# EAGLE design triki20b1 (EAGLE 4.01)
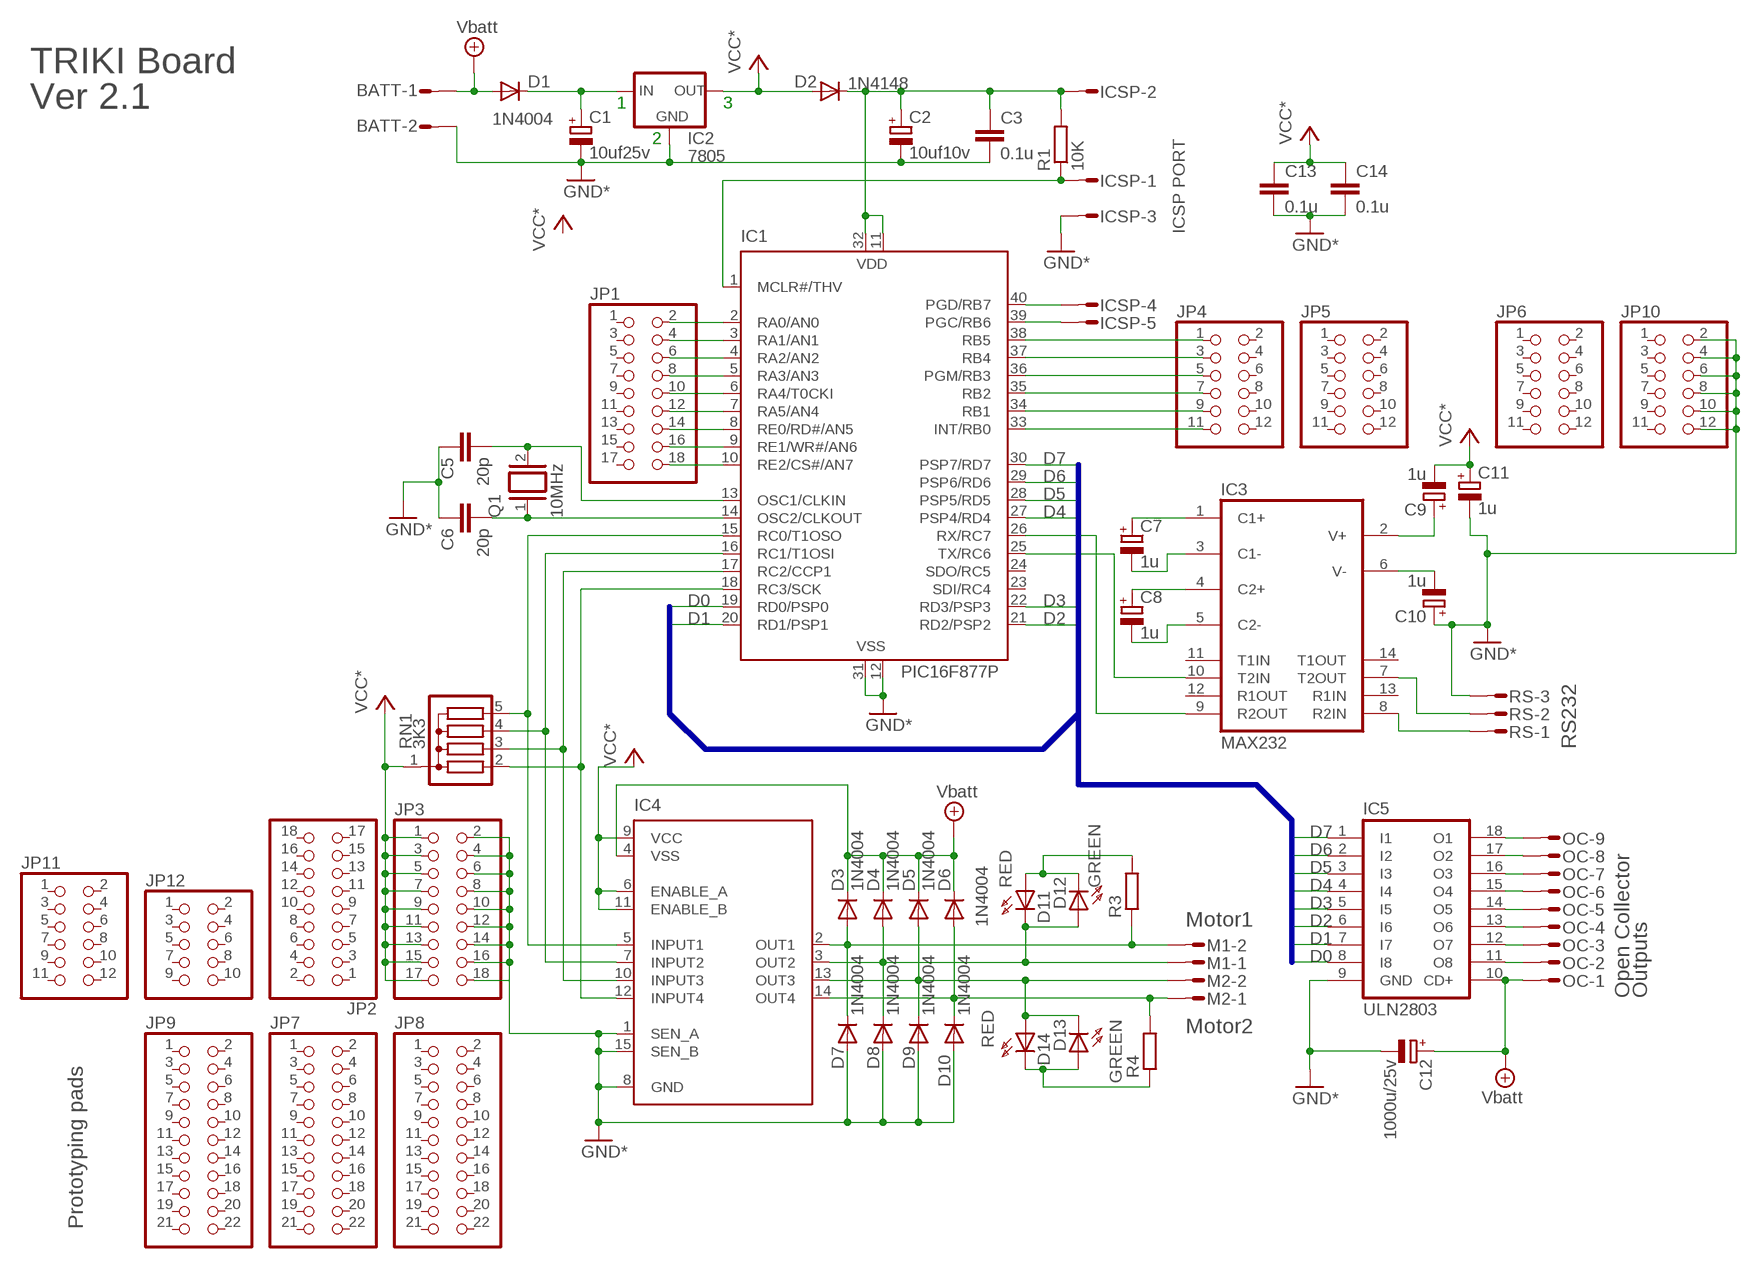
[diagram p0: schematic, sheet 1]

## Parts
BATT  S02P  [S02P]
C1  10uf25v  CPOL-EUE2-4  [E2-4]
C2  10uf10v  CPOL-EUE2-4  [E2-4]
C3  0.1u  C-EU025-025X050  [C025-025X050]
C5  20p  C-EU025-024X044  [C025-024X044]
C6  20p  C-EU025-024X044  [C025-024X044]
C7  1u  CPOL-EUE2-4  [E2-4]
C8  1u  CPOL-EUE2-4  [E2-4]
C9  1u  CPOL-EUE2-4  [E2-4]
C10  1u  CPOL-EUE2-4  [E2-4]
C11  1u  CPOL-EUE2-4  [E2-4]
C12  1000u/25v  CPOL-EUE3.5-10  [E3,5-10]
C13  0.1u  C-EU025-025X050  [C025-025X050]
C14  0.1u  C-EU025-025X050  [C025-025X050]
D1  1N4004  [DO41-10]
D2  1N4148  [DO35-10]
D3  1N4004  [DO41-10]
D4  1N4004  [DO41-10]
D5  1N4004  [DO41-10]
D6  1N4004  [DO41-10]
D7  1N4004  [DO41-10]
D8  1N4004  [DO41-10]
D9  1N4004  [DO41-10]
D10  1N4004  [DO41-10]
D11  RED  LED2X5  [LED2X5]
D12  GREEN  LED2X5  [LED2X5]
D13  GREEN  LED2X5  [LED2X5]
D14  RED  LED2X5  [LED2X5]
IC1  PIC16F877P  [DIL40]
IC2  7805  78XXS  [78XXS]
IC3  MAX232  [DIL16]
IC4  L298  [MW-15]
IC5  ULN2803  ULN2803A  [DIL18]
ICSP  S05P  [S05P]
JP1  PINHD-2X9  [2X09]
JP2  PINHD-2X9  [2X09]
JP3  PINHD-2X9  [2X09]
JP4  PINHD-2X6  [2X06]
JP5  PINHD-2X6  [2X06]
JP6  PINHD-2X6  [2X06]
JP7  PINHD-2X11  [2X11]
JP8  PINHD-2X11  [2X11]
JP9  PINHD-2X11  [2X11]
JP10  PINHD-2X6  [2X06]
JP11  PINHD-2X6  [2X06]
JP12  PINHD-2X5  [2X05]
M1  S02P  [S02P]
M2  S02P  [S02P]
OC  S09P  [S09P]
Q1  10MHz  XTAL/S  [QS]
R1  10K  R-EU_0204/7  [0204/7]
R3  R-EU_0204/7  [0204/7]
R4  R-EU_0204/7  [0204/7]
RN1  3K3  G04R  [SIL5]
RS  S03P  [S03P]

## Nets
+12V: BATT.1 C12.+ D1.A D3.K(C) D4.K(C) D5.K(C) D6.K(C) IC4.4(VSS) IC5.10(CD+) OC.1 ; supply symbol labelled Vbatt
D0: IC1.19(RD0/PSP0) IC5.8(I8)
D1: IC1.20(RD1/PSP1) IC5.7(I7)
D2: IC1.21(RD2/PSP2) IC5.6(I6)
D3: IC1.22(RD3/PSP3) IC5.5(I5)
D4: IC1.27(PSP4/RD4) IC5.4(I4)
D5: IC1.28(PSP5/RD5) IC5.3(I3)
D6: IC1.29(PSP6/RD6) IC5.2(I2)
D7: IC1.30(PSP7/RD7) IC5.1(I1)
GND: BATT.2 C1.- C2.- C3.1 C5.2 C6.2 C10.+ C11.- C12.- C13.1 C14.1 D7.A D8.A D9.A D10.A IC1.12(VSS) IC1.31(VSS) IC2.GND IC4.1(SEN_A) IC4.8(GND) IC4.15(SEN_B) IC5.9(GND) ICSP.3 JP3.2 JP3.4 JP3.6 JP3.8 JP3.10 JP3.12 JP3.14 JP3.16 JP3.18 JP10.2 JP10.4 JP10.6 JP10.8 JP10.10 JP10.12 RS.3 ; supply symbol labelled GND*
N$1: IC1.1(MCLR#/THV) ICSP.1 R1.1
N$2: C1.+ D1.K(C) IC2.IN
N$3: IC5.18(O1) OC.9
N$4: C5.1 IC1.13(OSC1/CLKIN) Q1.2
N$5: IC1.40(PGD/RB7) ICSP.4
N$6: IC1.39(PGC/RB6) ICSP.5
N$7: C10.- IC3.6(V-)
N$8: IC5.17(O2) OC.8
N$9: IC1.25(TX/RC6) IC3.10(T2IN)
N$10: C8.- IC3.5(C2-)
N$11: C8.+ IC3.4(C2+)
N$12: C7.- IC3.3(C1-)
N$13: C7.+ IC3.1(C1+)
N$14: IC3.7(T2OUT) RS.2
N$15: IC1.26(RX/RC7) IC3.9(R2OUT)
N$16: IC3.8(R2IN) RS.1
N$17: IC1.15(RC0/T1OSO) IC4.5(INPUT1) RN1.5
N$20: IC1.16(RC1/T1OSI) IC4.7(INPUT2) RN1.4
N$21: IC1.17(RC2/CCP1) IC4.10(INPUT3) RN1.3
N$22: IC1.18(RC3/SCK) IC4.12(INPUT4) RN1.2
N$23: D3.A D7.K(C) IC4.2(OUT1) M1.2 R3.1
N$24: D4.A D8.K(C) D11.K(C) D12.A IC4.3(OUT2) M1.1
N$25: D5.A D9.K(C) D13.K(C) D14.A IC4.13(OUT3) M2.2
N$26: D6.A D10.K(C) IC4.14(OUT4) M2.1 R4.2
N$27: IC5.16(O3) OC.7
N$28: IC5.15(O4) OC.6
N$29: D13.A D14.K(C) R4.1
N$30: D11.A D12.K(C) R3.2
N$31: IC5.14(O5) OC.5
N$32: IC5.13(O6) OC.4
N$33: IC5.12(O7) OC.3
N$34: C6.1 IC1.14(OSC2/CLKOUT) Q1.1
N$35: IC5.11(O8) OC.2
N$36: IC1.38(RB5) JP4.1
N$37: IC1.37(RB4) JP4.3
N$38: IC1.36(PGM/RB3) JP4.5
N$39: IC1.35(RB2) JP4.7
N$40: IC1.34(RB1) JP4.9
N$41: IC1.33(INT/RB0) JP4.11
N$42: IC1.2(RA0/AN0) JP1.2
N$43: IC1.3(RA1/AN1) JP1.4
N$44: IC1.4(RA2/AN2) JP1.6
N$45: IC1.5(RA3/AN3) JP1.8
N$46: IC1.6(RA4/T0CKI) JP1.10
N$47: IC1.7(RA5/AN4) JP1.12
N$48: IC1.8(RE0/RD#/AN5) JP1.14
N$49: IC1.9(RE1/WR#/AN6) JP1.16
N$50: IC1.10(RE2/CS#/AN7) JP1.18
N$51: C9.+ IC3.2(V+)
VCC: C9.- C11.+ C13.2 C14.2 D2.A IC2.OUT IC4.6(ENABLE_A) IC4.9(VCC) IC4.11(ENABLE_B) JP3.1 JP3.3 JP3.5 JP3.7 JP3.9 JP3.11 JP3.13 JP3.15 JP3.17 RN1.1 ; supply symbol labelled VCC*
VDD: C2.+ C3.2 D2.K(C) IC1.11(VDD) IC1.32(VDD) ICSP.2 R1.2
Unconnected: IC1.23(SDI/RC4) IC1.24(SDO/RC5) IC3.11(T1IN) IC3.12(R1OUT) IC3.13(R1IN) IC3.14(T1OUT) JP1.1 JP1.3 JP1.5 JP1.7 JP1.9 JP1.11 JP1.13 JP1.15 JP1.17 JP2.1 JP2.2 JP2.3 JP2.4 JP2.5 JP2.6 JP2.7 JP2.8 JP2.9 JP2.10 JP2.11 JP2.12 JP2.13 JP2.14 JP2.15 JP2.16 JP2.17 JP2.18 JP4.2 JP4.4 JP4.6 JP4.8 JP4.10 JP4.12 JP5.1 JP5.2 JP5.3 JP5.4 JP5.5 JP5.6 JP5.7 JP5.8 JP5.9 JP5.10 JP5.11 JP5.12 JP6.1 JP6.2 JP6.3 JP6.4 JP6.5 JP6.6 JP6.7 JP6.8 JP6.9 JP6.10 JP6.11 JP6.12 JP7.1 JP7.2 JP7.3 JP7.4 JP7.5 JP7.6 JP7.7 JP7.8 JP7.9 JP7.10 JP7.11 JP7.12 JP7.13 JP7.14 JP7.15 JP7.16 JP7.17 JP7.18 JP7.19 JP7.20 JP7.21 JP7.22 JP8.1 JP8.2 JP8.3 JP8.4 JP8.5 JP8.6 JP8.7 JP8.8 JP8.9 JP8.10 JP8.11 JP8.12 JP8.13 JP8.14 JP8.15 JP8.16 JP8.17 JP8.18 JP8.19 JP8.20 JP8.21 JP8.22 JP9.1 JP9.2 JP9.3 JP9.4 JP9.5 JP9.6 JP9.7 JP9.8 JP9.9 JP9.10 JP9.11 JP9.12 JP9.13 JP9.14 JP9.15 JP9.16 JP9.17 JP9.18 JP9.19 JP9.20 JP9.21 JP9.22 JP10.1 JP10.3 JP10.5 JP10.7 JP10.9 JP10.11 JP11.1 JP11.2 JP11.3 JP11.4 JP11.5 JP11.6 JP11.7 JP11.8 JP11.9 JP11.10 JP11.11 JP11.12 JP12.1 JP12.2 JP12.3 JP12.4 JP12.5 JP12.6 JP12.7 JP12.8 JP12.9 JP12.10

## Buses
D[0..7]

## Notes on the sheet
- TRIKI Board
- Ver 2.1 | 1 | 3
- 2
- ICSP PORT
- RS232
- Motor1
- Open Collector | Outputs
- Motor2
- Prototyping pads

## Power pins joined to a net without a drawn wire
GND: IC3.15(GND)
VCC: IC3.16(VCC)

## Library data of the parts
BATT M1 M2 = con-amp-mt:S02P: AMP MT CONNECTOR
C1 C2 C7-C12 = rcl:CPOL-EU: POLARIZED CAPACITOR, European symbol
C3 C5 C6 C13 C14 = rcl:C-EU: CAPACITOR, European symbol
D1 D3-D10 = diode:1N4004: DIODE
D2 = diode:1N4148: DIODE
D11-D14 = led:LED2X5: LED
IC1 = microchip:PIC16F87*: MICROCONTROLLER
IC2 = v-reg:78XXS: VOLTAGE REGULATOR
IC3 = maxim:MAX232: RS232 TRANSEIVER
IC4 = st-microelectronics:L298: DUAL FULL-BRIDGE DRIVER
IC5 = uln-udn:ULN2803A: DRIVER ARRAY
ICSP = con-amp-mt:S05P: AMP MT CONNECTOR
JP1-JP3 = pinhead:PINHD-2X9: PIN HEADER
JP4-JP6 JP10 JP11 = pinhead:PINHD-2X6: PIN HEADER
JP7-JP9 = pinhead:PINHD-2X11: PIN HEADER
JP12 = pinhead:PINHD-2X5: PIN HEADER
OC = con-amp-mt:S09P: AMP MT CONNECTOR
Q1 = special:XTAL/S: CRYSTAL
R1 R3 R4 = rcl:R-EU_: RESISTOR, European symbol
RN1 = resistor-sil:G04R: SIL RESISTOR
RS = con-amp-mt:S03P: AMP MT CONNECTOR

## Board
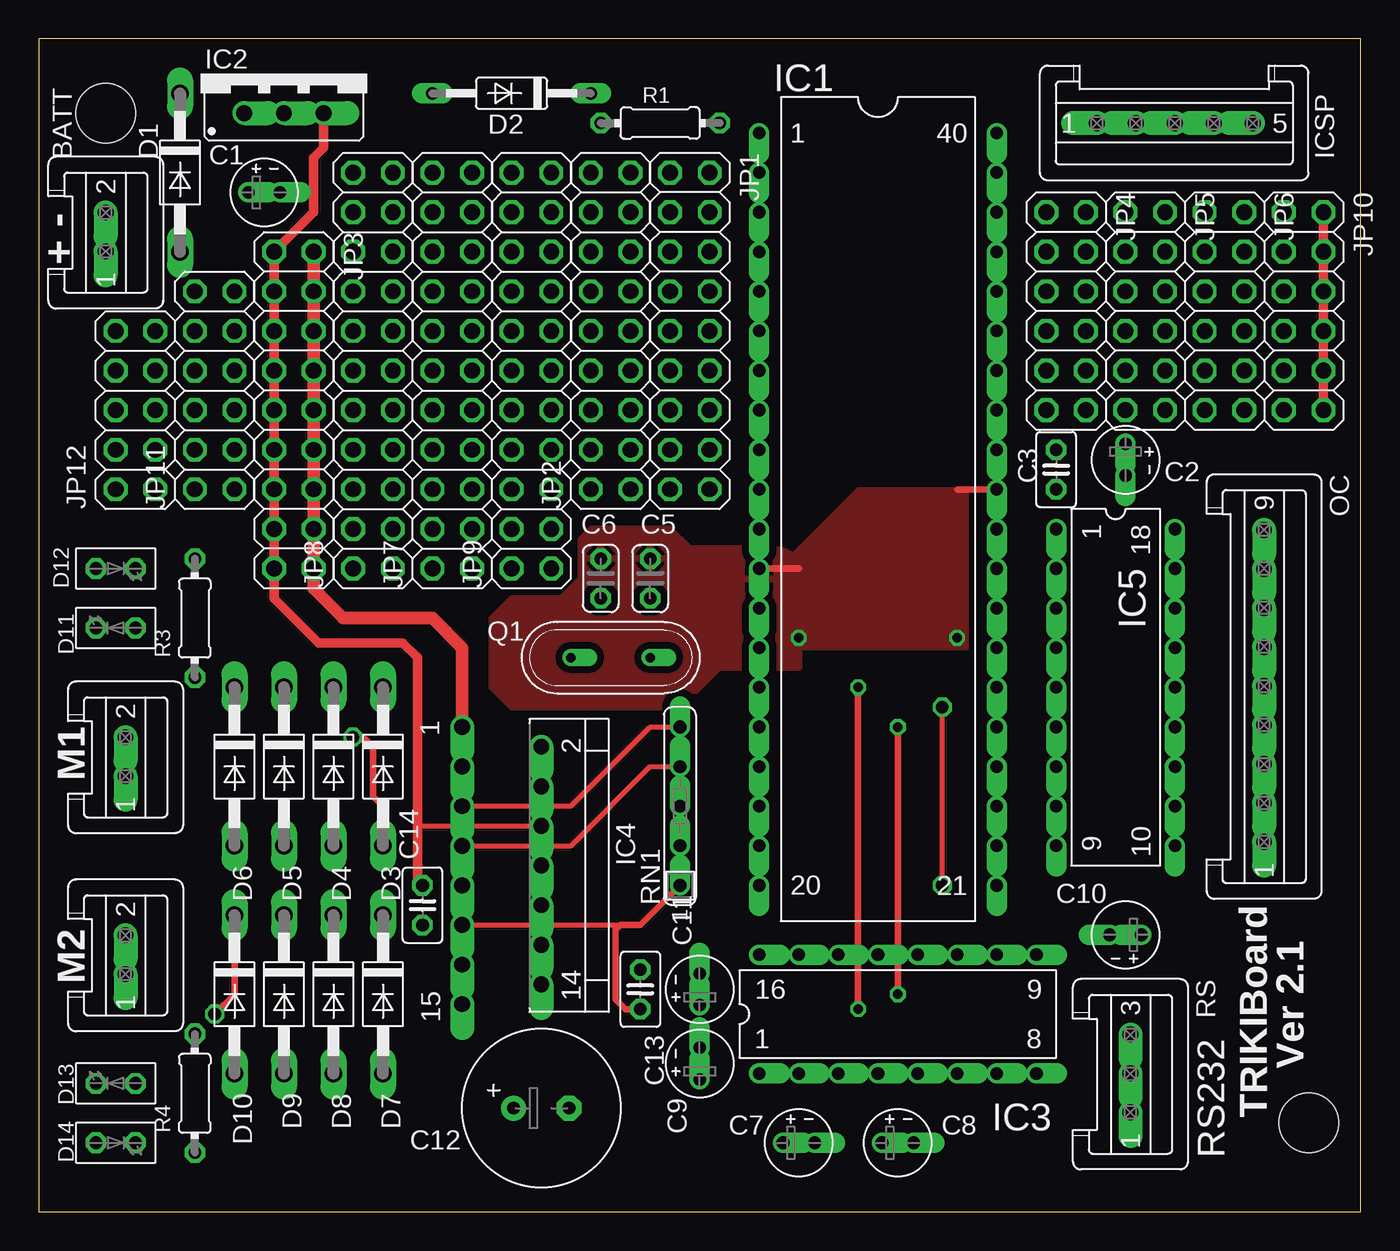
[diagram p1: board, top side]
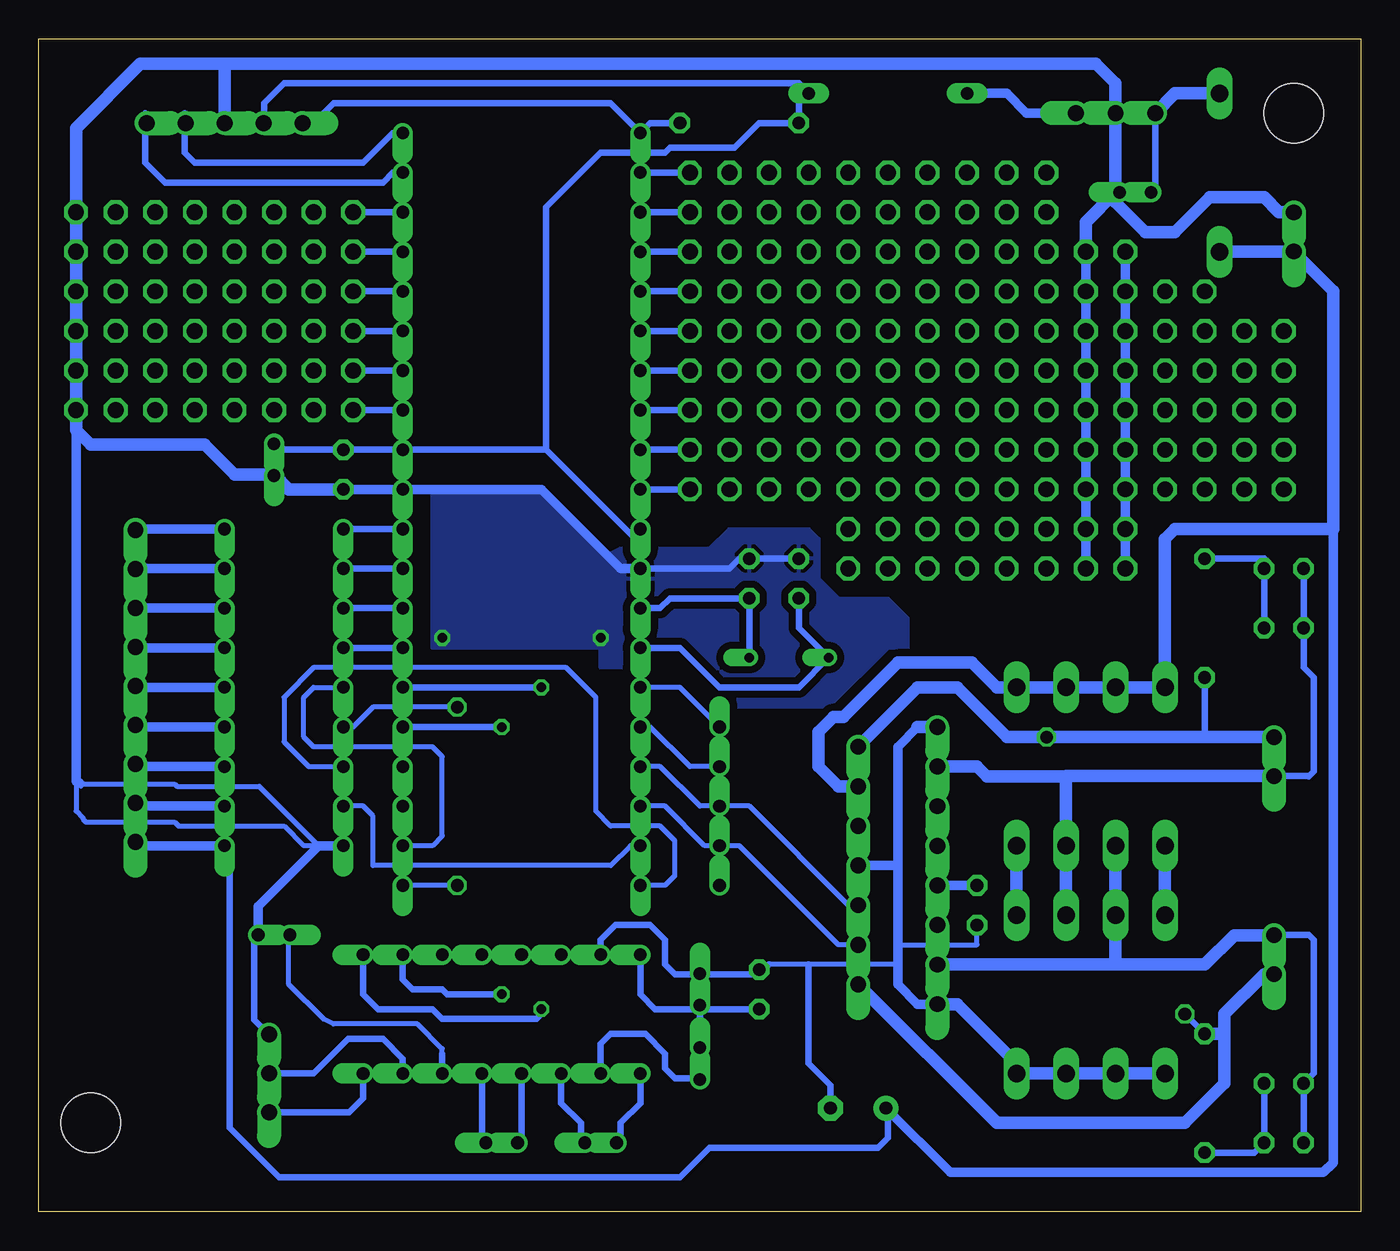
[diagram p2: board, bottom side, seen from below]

Size 84.76 x 75.24 mm. Coordinates in mm from the lower left corner, seen from the top.
Outline: 0,0 84.76,0 84.76,75.24 0,75.24 0,0
Copper layers used: Top, Bottom
Holes 3.81 mm at 4.28,70.48 81.43,5.71

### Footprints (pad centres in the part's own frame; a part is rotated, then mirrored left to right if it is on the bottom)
S02P = drill 1.016 offset: 1 1.25,0; 2 -1.25,0
E2-4 = drill 0.813 pad 1.27 offset: + -1.016,0; - 1.016,0
C025-025X050 = drill 0.813 octagon: 1 -1.27,0; 2 1.27,0
C025-024X044 = drill 0.813 octagon: 1 -1.27,0; 2 1.27,0
E3,5-10 = drill 0.813 pad 1.6 round: + -1.778,0 | drill 0.813 pad 1.6 octagon: - 1.778,0
DO41-10 = drill 1.118 long: A 5.08,0; K -5.08,0
DO35-10 = drill 0.813 long: A 5.08,0; K -5.08,0
LED2X5 = drill 0.813 octagon: A -1.27,0; K 1.27,0
DIL40 = drill 0.813 offset: 1 -24.13,-7.62; 2 -21.59,-7.62; 3 -19.05,-7.62; 4 -16.51,-7.62; 5 -13.97,-7.62; 6 -11.43,-7.62; 7 -8.89,-7.62; 8 -6.35,-7.62; 9 -3.81,-7.62; 10 -1.27,-7.62; 11 1.27,-7.62; 12 3.81,-7.62; 13 6.35,-7.62; 14 8.89,-7.62; 15 11.43,-7.62; 16 13.97,-7.62; 17 16.51,-7.62; 18 19.05,-7.62; 19 21.59,-7.62; 20 24.13,-7.62; 21 24.13,7.62; 22 21.59,7.62; 23 19.05,7.62; 24 16.51,7.62; 25 13.97,7.62; 26 11.43,7.62; 27 8.89,7.62; 28 6.35,7.62; 29 3.81,7.62; 30 1.27,7.62; 31 -1.27,7.62; 32 -3.81,7.62; 33 -6.35,7.62; 34 -8.89,7.62; 35 -11.43,7.62; 36 -13.97,7.62; 37 -16.51,7.62; 38 -19.05,7.62; 39 -21.59,7.62; 40 -24.13,7.62
78XXS = drill 1.016 offset: GND 0,-2.54; IN -2.54,-2.54; OUT 2.54,-2.54
DIL16 = drill 0.813 offset: 1 -8.89,-3.81; 2 -6.35,-3.81; 3 -3.81,-3.81; 4 -1.27,-3.81; 5 1.27,-3.81; 6 3.81,-3.81; 7 6.35,-3.81; 8 8.89,-3.81; 9 8.89,3.81; 10 6.35,3.81; 11 3.81,3.81; 12 1.27,3.81; 13 -1.27,3.81; 14 -3.81,3.81; 15 -6.35,3.81; 16 -8.89,3.81
MW-15 = drill 1.016 offset: 1 -8.89,-7.62; 2 -7.62,-2.54; 3 -6.35,-7.62; 4 -5.08,-2.54; 5 -3.81,-7.62; 6 -2.54,-2.54; 7 -1.27,-7.62; 8 0,-2.54; 9 1.27,-7.62; 10 2.54,-2.54; 11 3.81,-7.62; 12 5.08,-2.54; 13 6.35,-7.62; 14 7.62,-2.54; 15 8.89,-7.62
DIL18 = drill 0.813 offset: 1 -10.16,-3.81; 2 -7.62,-3.81; 3 -5.08,-3.81; 4 -2.54,-3.81; 5 0,-3.81; 6 2.54,-3.81; 7 5.08,-3.81; 8 7.62,-3.81; 9 10.16,-3.81; 10 10.16,3.81; 11 7.62,3.81; 12 5.08,3.81; 13 2.54,3.81; 14 0,3.81; 15 -2.54,3.81; 16 -5.08,3.81; 17 -7.62,3.81; 18 -10.16,3.81
S05P = drill 1.016 offset: 1 5,0; 2 2.5,0; 3 0,0; 4 -2.5,0; 5 -5,0
2X09 = drill 1.016 octagon: 1 -10.16,-1.27; 2 -10.16,1.27; 3 -7.62,-1.27; 4 -7.62,1.27; 5 -5.08,-1.27; 6 -5.08,1.27; 7 -2.54,-1.27; 8 -2.54,1.27; 9 0,-1.27; 10 0,1.27; 11 2.54,-1.27; 12 2.54,1.27; 13 5.08,-1.27; 14 5.08,1.27; 15 7.62,-1.27; 16 7.62,1.27; 17 10.16,-1.27; 18 10.16,1.27
2X06 = drill 1.016 octagon: 1 -6.35,-1.27; 2 -6.35,1.27; 3 -3.81,-1.27; 4 -3.81,1.27; 5 -1.27,-1.27; 6 -1.27,1.27; 7 1.27,-1.27; 8 1.27,1.27; 9 3.81,-1.27; 10 3.81,1.27; 11 6.35,-1.27; 12 6.35,1.27
2X11 = drill 1.016 octagon: 1 -12.7,-1.27; 2 -12.7,1.27; 3 -10.16,-1.27; 4 -10.16,1.27; 5 -7.62,-1.27; 6 -7.62,1.27; 7 -5.08,-1.27; 8 -5.08,1.27; 9 -2.54,-1.27; 10 -2.54,1.27; 11 0,-1.27; 12 0,1.27; 13 2.54,-1.27; 14 2.54,1.27; 15 5.08,-1.27; 16 5.08,1.27; 17 7.62,-1.27; 18 7.62,1.27; 19 10.16,-1.27; 20 10.16,1.27; 21 12.7,-1.27; 22 12.7,1.27
2X05 = drill 1.016 octagon: 1 -5.08,-1.27; 2 -5.08,1.27; 3 -2.54,-1.27; 4 -2.54,1.27; 5 0,-1.27; 6 0,1.27; 7 2.54,-1.27; 8 2.54,1.27; 9 5.08,-1.27; 10 5.08,1.27
S09P = drill 1.016 offset: 1 0,0; 2 -2.5,0; 3 -5,0; 4 -7.5,0; 5 -10,0; 6 -12.5,0; 7 -15,0; 8 -17.5,0; 9 -20,0
QS = drill 0.61 offset: 1 -2.54,0; 2 2.54,0
0204/7 = drill 0.813 octagon: 1 -3.81,0; 2 3.81,0
SIL5 = drill 0.813 offset: 1 -5.08,0; 2 -2.54,0; 3 0,0; 4 2.54,0; 5 5.08,0
S03P = drill 1.016 offset: 1 2.5,0; 2 0,0; 3 -2.5,0

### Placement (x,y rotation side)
BATT  4.28,62.86 270 top
C1  14.44,65.4 0 top
C2  69.69,48.25 270 top
C3  65.24,47.62 90 top
C5  39.2,40.63 90 top
C6  36.03,40.63 90 top
C7  48.73,4.44 0 top
C8  55.08,4.44 0 top
C9  42.38,9.52 90 top
C10  69.69,17.78 180 top
C11  42.38,14.28 90 top
C12  32.22,6.66 0 top
C13  38.57,14.28 270 top
C14  24.6,19.68 90 top
D1  9.04,66.67 270 top
D2  30.31,71.75 180 top
D3  22.06,28.57 270 top
D4  18.88,28.57 270 top
D5  15.71,28.57 270 top
D6  12.54,28.57 270 top
D7  22.06,13.96 270 top
D8  18.88,13.96 270 top
D9  15.71,13.96 270 top
D10  12.54,13.96 270 top
D11  4.92,37.46 180 top
D12  4.92,41.27 0 top
D13  4.92,8.25 180 top
D14  4.92,4.44 0 top
IC1  53.81,45.08 270 top
IC2  15.71,73.02 0 top
IC3  55.08,12.7 0 top
IC4  34.76,22.22 270 top
IC5  69.05,33.65 270 top
ICSP  72.86,69.84 180 top
JP1  41.74,56.51 270 top
JP2  36.66,56.51 90 top
JP3  16.34,51.43 270 top
JP4  65.88,57.78 270 top
JP5  70.95,57.78 270 top
JP6  76.03,57.78 270 top
JP7  26.5,53.97 90 top
JP8  21.42,53.97 90 top
JP9  31.58,53.97 90 top
JP10  81.11,57.78 270 top
JP11  11.27,52.7 90 top
JP12  6.18,51.43 90 top
M1  5.55,29.21 270 top
M2  5.55,16.5 270 top
OC  78.58,23.74 270 top
Q1  36.66,35.55 0 top
R1  39.84,69.84 180 top
R3  10,38.09 90 top
R4  10,7.61 90 top
RN1  41.11,26.03 90 top
RS  70,8.89 270 top

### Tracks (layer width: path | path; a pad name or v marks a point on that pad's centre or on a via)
+12V
  Bottom 0.406: 78.32,23.49 OC.1 | IC5.10 72.54,23.17 72.54,5.39 69.37,2.22 43.65,2.22 41.74,4.12 30.95,4.12 30.31,4.76 30.31,6.34
  Bottom 0.61: IC5.10 78.32,23.49 | 6.17,61.61 5.89,61.61 5.87,61.59 D1.A | 1.74,43.81 1.74,3.17 2.38,2.54 26.31,2.54 C12.+ 30.31,6.54 30.31,6.34 30.31,6.66 | BATT.1 4.28,61.59 4.92,61.59
  Bottom 0.813: 6.17,61.61 BATT.1 9.02,61.61 D1.A | IC4.4 33.49,27.3 34.76,28.57 34.76,30.79 33.81,31.75 33.17,31.75 29.68,35.24 24.92,35.24 23.33,33.65 D3.K D4.K D5.K D6.K 12.54,43.17 11.9,43.81 1.74,43.81 | 1.74,43.81 1.74,44.13 | 1.74,43.81 1.74,59.05 4.28,61.59
D0
  Bottom 0.305: IC5.8 63.97,26.03 63.34,25.39 63.34,22.22 48.09,22.22 46.82,23.49 IC1.19
D1
  Bottom 0.305: IC1.20 44.6,20.95 43.97,21.59 43.97,23.81 44.92,24.76 48.09,24.76 49.05,25.71 49.05,33.02 50.95,34.92 67.14,34.92 69.05,33.02 69.05,30.16 67.46,28.57 IC5.7
D2  (via drill 0.81)
  Top 0.305: v57.94,20.95 v57.94,32.38
  Bottom 0.305: v57.94,20.95 IC1.21 | v57.94,32.38 63.34,32.38 64.61,31.11 IC5.6
D3
  Bottom 0.305: IC1.22 59.52,23.49 58.89,24.12 58.89,29.21 59.52,29.84 67.14,29.84 67.78,30.47 67.78,33.02 67.14,33.65 IC5.5
D4
  Bottom 0.406: IC1.27 IC5.4
D5
  Bottom 0.406: IC1.28 IC5.3
D6
  Bottom 0.406: IC1.29 IC5.2
D7
  Bottom 0.406: IC1.30 IC5.1
GND  (via drill 0.61)
  Top 0.406: IC1.12 48.73,41.27 | IC1.31 58.89,46.35
  Top 0.61: JP10.2 JP10.12
  Top 0.813: JP3.2 JP3.4 JP3.6 | JP3.6 17.61,56.19 | JP3.6 JP3.8 JP3.10 JP3.12 JP3.14 | JP3.14 17.61,46.03 | JP3.14 JP3.16 JP3.18 17.61,40 19.52,38.09 25.23,38.09 27.14,36.19 IC4.1
  Bottom 0.305: C14.1 24.6,17.14 29.68,17.14 | 29.68,15.87 35.39,15.87 37.94,15.87 | 82.07,27.62 82.39,27.62 82.39,25.71 81.95,25.28 81.95,25.22 81.75,25.01 76.06,25.01 75.81,24.76 69.05,24.76 67.78,23.49 66.19,23.49 | 82.07,27.62 82.07,27.3 | 82.07,27.62 81.9,27.45 76.06,27.45 75.91,27.3 70.64,27.3 66.83,23.49
  Bottom 0.406: IC3.15 48.73,17.46 47.78,18.41 45.55,18.41 44.6,17.46 44.6,15.87 43.97,15.23 42.38,15.23 C11.- 42.32,15.23 38.57,15.23 | 38.57,15.23 C13.1 | 37.94,15.87 38.57,15.23 | RS.3 70.95,12.34 70.95,17.78 C10.+ | C12.- 34,8.12 35.39,9.52 35.39,15.87 | IC1.12 40.48,41.27 39.84,41.9 C5.2 C6.2
  Bottom 0.61: C3.1 IC1.31 52.54,46.35 47.46,41.27 IC1.12 | 28.41,31.11 29.68,29.84 29.68,22.22 | 29.68,22.22 IC4.8 | 29.68,22.22 29.68,17.14 29.68,15.87 29.68,14.6 28.41,13.33 IC4.15 | 70.32,47.3 69.69,47.3 | JP3.18 17.61,61.91 | C10.+ 70.7,19.62 66.83,23.49 66.19,23.49 IC5.9 | JP10.12 82.39,27.62
  Bottom 0.813: D10.A D9.A D8.A D7.A 22.06,9.52 25.87,13.33 IC4.15 | 15.71,65.4 IC2.GND 15.71,72.38 16.98,73.66 72.86,73.66 | BATT.2 4.28,64.13 5.23,64.13 6.18,65.08 9.68,65.08 11.9,62.86 13.81,62.86 15.71,64.77 15.71,65.08 15.39,65.4 C1.- 15.71,65.4 | 28.41,31.11 IC4.1 | 15.71,65.4 17.61,63.49 17.61,61.91 JP3.2 | 72.86,73.66 78.26,73.66 82.39,69.53 JP10.2 JP10.4 JP10.6 JP10.8 JP10.10 JP10.12 82.39,50.16 81.43,49.21 74.13,49.21 72.22,47.3 70.32,47.3 70,47.3 | 72.86,73.66 ICSP.3 | C2.- 69.69,47.3 68.73,46.35 C3.1
  other vias: 48.73,36.82 58.89,36.82
  pour Bottom: 48.09,41.27 48.09,36.19 59.52,36.19 59.52,46.35 52.54,46.35 48.09,41.9
  pour Top: 48.09,41.9 48.09,36.19 59.52,36.19 59.52,46.35 61.43,46.35 52.54,46.35
  pour Top (isolate 0.457): 29.04,38.09 29.04,33.65 30.31,32.38 41.11,32.38 42.38,33.65 43.65,34.92 48.73,34.92 48.73,41.9 47.46,42.54 41.74,42.54 40.48,43.81 35.39,43.81 34.76,43.17 34.76,40.63 33.49,39.36 30.31,39.36
  pour Bottom (isolate 0.457): 29.04,38.09 29.04,36.19 30.31,36.19 34.12,32.38 41.11,32.38 43.65,34.92 48.73,34.92 48.73,41.9 47.46,42.54 41.74,42.54 40.48,43.81 35.39,43.81 34.76,43.17 34.76,40.63 33.49,39.36 30.31,39.36
N$1
  Bottom 0.406: ICSP.1 67.14,69.84 65.88,71.11 48.09,71.11 IC1.1 45.55,69.84 R1.1
N$2
  Bottom 0.406: C1.+ 13.49,65.4 13.17,65.72 IC2.IN
  Bottom 0.813: D1.K 11.9,71.75 IC2.IN
N$3
  Bottom 0.406: 78.58,43.81 OC.9
  Bottom 0.61: IC5.18 78.58,43.81
N$4
  Bottom 0.406: Q1.2 C5.1 44.28,39.36 44.92,38.73 IC1.13
N$5
  Bottom 0.406: IC1.40 62.06,69.21 63.97,67.3 74.77,67.3 75.4,67.94 75.4,70.48 ICSP.4
N$6
  Bottom 0.406: IC1.39 62.06,66.67 62.7,66.03 76.67,66.03 77.94,67.3 77.94,70.48 ICSP.5
N$7
  Bottom 0.305: 68.73,17.78 68.73,14.6 66.51,12.38 65.88,12.06 60.48,12.06 58.89,10.47 58.89,10.16
  Bottom 0.406: IC3.6 58.89,10.16 | 68.73,17.78 C10.-
N$8
  Bottom 0.406: 78.55,41.27 OC.8
  Bottom 0.61: IC5.17 78.55,41.27
N$9  (via drill 0.61)
  Top 0.406: v55.08,13.96 v55.08,31.11
  Bottom 0.406: IC3.10 61.43,14.92 60.8,14.28 58.89,14.28 58.57,13.96 v55.08,13.96 | v55.08,31.11 IC1.25
N$10
  Bottom 0.406: C8.- 56.35,4.44 IC3.5
N$11
  Bottom 0.406: C8.+ 53.81,4.44 IC3.4
N$12
  Bottom 0.406: IC3.3 51.27,6.98 50,5.71 50,4.44 C7.-
N$13
  Bottom 0.406: IC3.1 46.19,6.98 47.46,5.71 47.46,4.44 C7.+
N$14
  Bottom 0.406: RS.2 67.14,8.89 64.92,11.11 62.7,11.11 61.43,9.84 IC3.7
N$15  (via drill 0.61)
  Top 0.406: v52.54,13.01 v52.54,33.65
  Bottom 0.406: IC3.9 63.97,13.96 63.02,13.01 59.52,13.01 58.89,12.38 52.86,12.38 52.54,12.7 v52.54,13.01 | v52.54,33.65 IC1.26
N$16
  Bottom 0.406: RS.1 64.88,6.39 63.97,7.3 IC3.8
N$17
  Top 0.305: IC4.5 34.12,26.03 39.2,31.11 RN1.5
  Bottom 0.305: RN1.5 43.65,33.65 IC1.15
N$20
  Top 0.305: IC4.7 34.12,23.49 39.2,28.57 RN1.4
  Bottom 0.305: RN1.4 43.02,28.57 45.55,31.11 IC1.16
N$21
  Bottom 0.305: IC4.10 32.85,19.68 39.2,26.03 RN1.3 42.38,26.03 44.92,28.57 IC1.17
N$22
  Bottom 0.305: IC4.12 33.49,17.14 39.84,23.49 RN1.2 42.06,23.49 44.6,26.03 IC1.18
N$23  (via drill 0.81)
  Top 0.406: D3.A 22.06,26.03 21.42,26.66 21.42,29.84 20.79,30.47 20.15,30.47 v20.13,30.46
  Bottom 0.406: M1.2 10,30.46 R3.1
  Bottom 0.813: D3.A D7.K | M1.2 v20.13,30.46 | v20.13,30.46 20.15,30.47 | v20.13,30.46 22.67,30.46 25.87,33.65 28.41,33.65 IC4.2
N$24
  Bottom 0.406: D12.A D11.K 3.64,34.92 3.01,34.28 3.01,28.25 3.33,27.93 3.33,27.96 M1.1
  Bottom 0.813: D8.K D4.A 18.88,27.93 | M1.1 18.86,27.96 18.88,27.93 | IC4.3 24.6,28.57 23.96,27.93 18.88,27.93
N$25
  Bottom 0.406: D14.A D13.K 3.01,8.89 3.01,17.46 3.33,17.78 5.55,17.78 M2.2
  Bottom 0.813: D5.A D9.K 15.71,15.87 | M2.2 8.11,17.75 10,15.87 15.71,15.87 | 15.71,15.87 IC4.13
N$26  (via drill 0.81)
  Top 0.406: D10.K 12.54,13.96 v11.27,12.7
  Bottom 0.406: R4.2 v11.27,12.7
  Bottom 0.61: M2.1 5.57,15.23 6.18,15.23
  Bottom 0.813: D10.K D6.A | IC4.14 23.33,5.71 11.27,5.71 8.73,8.25 8.73,11.43 | 8.73,11.43 8.73,12.7 6.18,15.23 5.55,15.23 | 8.73,11.43 R4.2
N$27
  Bottom 0.406: 78.56,38.73 OC.7
  Bottom 0.61: IC5.16 78.56,38.73
N$28
  Bottom 0.406: 78.52,36.19 OC.6
  Bottom 0.61: IC5.15 78.52,36.19
N$29
  Bottom 0.406: R4.1 6.82,3.81 D14.K D13.A
N$30
  Bottom 0.406: D11.A D12.K 6.18,41.9 R3.2
N$31
  Bottom 0.406: 78.58,33.65 OC.5
  Bottom 0.61: IC5.14 78.58,33.65
N$32
  Bottom 0.406: 78.58,31.11 OC.4
  Bottom 0.61: IC5.13 78.58,31.11
N$33
  Bottom 0.406: 78.58,28.57 OC.3
  Bottom 0.61: IC5.12 78.58,28.57
N$34
  Bottom 0.406: IC1.14 43.65,36.19 41.11,33.65 36.03,33.65 Q1.1 36.03,37.46 C6.1
N$35
  Bottom 0.406: 78.58,26.03 OC.2
  Bottom 0.61: IC5.11 78.58,26.03
N$36
  Bottom 0.406: IC1.38 JP4.1
N$37
  Bottom 0.406: IC1.37 JP4.3
N$38
  Bottom 0.406: IC1.36 JP4.5
N$39
  Bottom 0.406: IC1.35 JP4.7
N$40
  Bottom 0.406: IC1.34 JP4.9
N$41
  Bottom 0.406: IC1.33 JP4.11
N$42
  Bottom 0.406: JP1.2 IC1.2
N$43
  Bottom 0.406: JP1.4 IC1.3
N$44
  Bottom 0.406: JP1.6 IC1.4
N$45
  Bottom 0.406: JP1.8 IC1.5
N$46
  Bottom 0.406: JP1.10 IC1.6
N$47
  Bottom 0.406: JP1.12 IC1.7
N$48
  Bottom 0.406: JP1.14 IC1.8
N$49
  Bottom 0.406: JP1.16 IC1.9
N$50
  Bottom 0.406: JP1.18 IC1.10
N$51
  Bottom 0.406: IC3.2 48.73,10.79 48.09,11.43 45.87,11.43 44.6,10.16 44.6,9.2 43.97,8.57 43.02,8.57 42.38,8.57 C9.+
VCC
  Top 0.305: IC4.11 37.3,18.41 | 24.28,24.76 IC4.6
  Top 0.406: C13.2 37.62,13.01 36.98,13.65 36.98,18.09 37.3,18.41 38.57,18.41 RN1.1
  Top 0.61: IC2.OUT 18.25,68.26 17.61,67.62 17.61,64.13 JP3.1 JP3.3 JP3.5 JP3.7 JP3.9 JP3.11 JP3.13 JP3.15 JP3.17 15.08,39.36 17.93,36.51 23.33,36.51 24.28,35.55 24.28,24.76 24.28,21.27 C14.2
  Bottom 0.406: C11.+ 42.38,13.33 | C11.+ C9.- | C11.+ 42.63,13.01 45.24,13.01 46.19,13.96 IC3.16 | C11.+ 42.13,13.01 C13.2
  Bottom 0.61: IC2.OUT 21.42,70.48 22.7,71.75 D2.A | C14.2 IC4.9 | JP3.17 JP3.1
  Bottom 0.813: IC4.9 IC4.11
VDD
  Bottom 0.406: ICSP.2 70.32,69.84 70.32,71.11 69.05,72.38 36.03,72.38 D2.K 36.03,71.11 R1.2 38.57,69.84 40.16,68.26 44.28,68.26 44.6,67.94 48.73,67.94 52.22,64.45 52.22,48.89 | C2.+ 69.69,49.52 69.05,48.89 C3.2 IC1.32 52.22,48.89 | 52.22,48.89 46.82,43.49 46.51,43.49 IC1.11

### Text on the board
tNames: - | + | TRIKIBoard | Ver 2.1 | RS232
